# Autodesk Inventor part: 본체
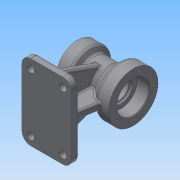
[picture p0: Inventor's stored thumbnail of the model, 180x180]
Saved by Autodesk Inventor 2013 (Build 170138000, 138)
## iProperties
Created: 2015-08
Part Number: 본체
Material: 일반
Document SubType Name: Modeling
Designer: Administrator
Density: 1 g/cm^3
Author: Administrator
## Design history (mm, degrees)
sketch "스케치1"
  geometry: L1 (0, 0)-(-40, 0); L2 (0, 0)-(50, 0); L3 (-40, 0)-(-40, 35); L4 (-40, 35)-(-20, 35); L5 (-20, 35)-(-14.804, 26); L6 (-14.804, 26)-(13.315, 26); L7 (13.315, 26)-(30, 40); L8 (30, 40)-(50, 40); L9 (50, 40)-(50, 0)
  constraints: 18 end point, 3 parallel, 2 perpendicular, 1 collinear, 1 horizontal
  dimensions: "d3" = 40 distance of L1.start L1.end; "d4" = 50 distance of L1.start L2.end; "d5" = 70 diameter of L4 L1; "d6" = 20 distance of L3.end L4.end; "d7" = 60 deg angle of L6 L5; "d8" = 52 diameter of L6 L1; "d9" = 80 diameter of L8 L2; "d10" = 20 distance of L7.end L8.end; "d11" = 40 deg angle of L6 L7
revolve "회전1" sketch "스케치1" stored, may be unused: angle "d12" = 90 deg
node "작업 평면1"
sketch "스케치2"
  geometry: L1 (40, 61)-(-40, 61); L2 (-40, 61)-(-40, -61); L3 (-40, -61)-(40, -61); L4 (40, -61)-(40, 61); L5 (40, 61)-(-40, -61); L6 (-40, 61)-(40, -61); 1 further point
  constraints: 12 end point, 2 midpoint, 2 parallel, 1 horizontal, 1 perpendicular
  dimensions: "d14" = 122 distance of L3.end L1.start; "d16" = 80 distance of L2.end L3.end
extrude "돌출1" join sketch "스케치2" distance "d17" = 12; taper "d18" = 0 deg
sketch "스케치3"
  geometry: L1 (-78, -61)-(-78, 61) reference; L2 (-90, -61)-(-78, -61) reference; L3 (-90, 85.4)-(-90, -85.4) reference; L4 (-6.815, -25.091)-(-78, -51); L5 (-78, 51)-(-6.815, 25.091); L6 (-90, 61)-(-78, 61) reference; C1 r 35 at (0, 0) reference; A1 r 26 centre (0, 0) between (-6.815, -25.091) and (-6.815, 25.091) reference; 1 further point
  constraints: 4 end point, 2 point on circle, 2 point on line
  dimensions: "d19" = 10 distance from line of L2 L4.end; "d20" = 70 deg angle of L1 L4; "d21" = 70 deg angle of L1 L5; "d22" = 10 distance from line of L6 L5.start
extrude "돌출2" join sketch "스케치3" stored distance "d23" = 12; taper "d24" = 0 deg
sketch "스케치4"
  geometry: L1 (-40, -35)-(-20, -35) reference; L2 (30, -40)-(50, -40) reference; L3 (13.315, -26)-(30, -40) reference; L4 (-14.804, -26)-(-14.804, 26) reference; L5 (-6, -6.815)-(-6, -6.815) reference; L6 (-6, -6.815)-(6, -6.815) reference; L7 (6, -6.815)-(6, -6.815) reference; L8 (6, -6.815)-(-6, -6.815) reference; L9 (13.315, -26)-(13.315, 26) reference; L10 (-14.804, -26)-(-14.804, 26) reference; L11 (-14.804, -26)-(-14.804, 26) reference; L12 (-20, -35)-(-20, 35) reference; L13 (40, -90)-(-40, -90) reference; L14 (-40, -90)-(-40, -78) reference; L15 (40, -78)-(-40, -78) reference; L16 (40, -90)-(40, -78) reference; L17 (-14.804, -26)-(13.315, -26) reference; L18 (-30, -78)-(-30, -35); L19 (30, -78)-(36.7, -40); 1 further point
  constraints: 4 end point, 3 point on line, 1 midpoint, 1 perpendicular
  dimensions: "d25" = 10 distance between parallel lines of L18 L14; "d26" = 80 deg angle of L15 L19; "d27" = 10 distance from line of L16 L19.start
  node "투영된 루프2"
  node "투영된 루프3"
  node "투영된 루프4"
feature "리브1" dims "d28" = 1, "d29" = 12, "d30" = 0, "d31" = 0, "d32" = 1, "d33" = 1
feature "리브2" dims "d34" = 1, "d35" = 12, "d36" = 0, "d37" = 0, "d38" = 1, "d39" = 1
sketch "스케치5"
  geometry: L1 (-6, -78)-(-6, -25.298) reference; L2 (-6, -78)-(-51, -78) reference; L3 (-6, -25.298)-(-6, -78) reference; L4 (-18, -54)-(-18, -60); L5 (-30, -54)-(-30, -60); A1 r 6 centre (-24, -54) between (-18, -54) and (-30, -54); A2 r 6 centre (-24, -60) between (-30, -60) and (-18, -60); A3 r 26 centre (0, 0) between (-25.091, -6.815) and (-6, -25.298) reference
  constraints: 4 end point, 4 point on circle, 2 centre point, 2 parallel, 2 tangent, 1 equal radius, 1 vertical alignment
  dimensions: "d40" = 12 diameter of A1; "d43" = 18 distance from line of L2 A2.centre; "d47" = 6 distance of A2.centre A1.centre; "d106" = 24 horizontal distance of A3.centre A2.centre
extrude "돌출3" cut sketch "스케치5" stored distance "d45" = 12; taper "d46" = 0 deg
sketch "스케치6"
  geometry: C1 r 40 at (0, 0) reference
hole "구멍1" sketch "스케치6" at (0, 0) diameter "d49" = 38; stored, may be unused: countersink angle "d53" = 90 deg, drill point angle "d55" = 0 deg; dims "d50" = 6, "d51" = 52, "d52" = 20, "d54" = 23
sketch "스케치7"
  geometry: C1 r 35 at (0, 0) reference
hole "구멍2" sketch "스케치7" at (0, 0) diameter "d56" = 32; stored, may be unused: countersink angle "d60" = 90 deg, drill point angle "d62" = 0 deg; dims "d57" = 6, "d58" = 40, "d59" = 17, "d61" = 23
sketch "스케치8"
  geometry: C1 r 26 at (0, 0) reference; 1 further point
  constraints: 1 vertical alignment
  dimensions: "d63" = 33 distance of C1.centre point (0, 33)
hole "구멍3" sketch "스케치8" at (0, 33) diameter "d64" = 3.242; stored, may be unused: countersink angle "d68" = 90 deg, drill point angle "d70" = 118 deg; dims "d65" = 10, "d66" = 40, "d67" = 17, "d69" = 13
sketch "스케치9"
  geometry: C1 r 20 at (0, 0) reference; 1 further point
  constraints: 1 vertical alignment
  dimensions: "d74" = 27 distance of C1.centre point (0, 27)
hole "구멍4" sketch "스케치9" at (0, 27) diameter "d75" = 3.242; stored, may be unused: countersink angle "d79" = 90 deg, drill point angle "d81" = 118 deg; dims "d76" = 10, "d77" = 40, "d78" = 17, "d80" = 13
chamfer "모따기1" distance "d85" = 1; stored, may be unused: second distance "d86" = 2, angle "d87" = 45 deg
fillet "모깎기1" dims "d88" = 0.3
fillet "모깎기2" dims "d89" = 3
fillet "모깎기3" dims "d90" = 0.3
fillet "모깎기4" dims "d91" = 5
fillet "모깎기5" dims "d92" = 14
sketch "스케치10"
  geometry: C1 r 6 at (26, 47); C2 r 6 at (26, -47); C3 r 6 at (-26, -47); C4 r 6 at (-26, 47); A1 r 14 centre (-26, -47) between (-40, -47) and (-26, -61) reference; A2 r 14 centre (26, -47) between (26, -61) and (40, -47) reference; A3 r 14 centre (26, 47) between (40, 47) and (26, 61) reference; A4 r 14 centre (-26, 47) between (-26, 61) and (-40, 47) reference; 1 further point
  constraints: 4 centre point, 4 coincident, 3 equal radius
  dimensions: "d93" = 12 diameter of C1
extrude "돌출4" cut sketch "스케치10" stored distance "d95" = 12; taper "d96" = 0 deg
fillet "모깎기6" dims "d97" = 3
fillet "모깎기7" dims "d98" = 3
fillet "모깎기8" dims "d99" = 3
fillet "모깎기9" dims "d100" = 5
fillet "모깎기10" dims "d101" = 3
sketch "스케치13"
  geometry: L1 (-3, 35.113)-(-3, 0) reference; L2 (-10, -3)-(1, -3) reference; 2 further points
  constraints: 1 other
  dimensions: "d102" = 16 distance from line of L1 point (13, 21); "d103" = 24 distance from line of point (13, 21) L2
feature "엠보싱1" sketch "스케치13" dims "d104" = 0.5, "d105" = 0
node "솔리드1"
mirror "대칭1"
pattern_circular "원형 패턴1" dims angle "d72" = 360 deg
pattern_circular "원형 패턴2" dims angle "d83" = 360 deg
node "투영된 루프1"
